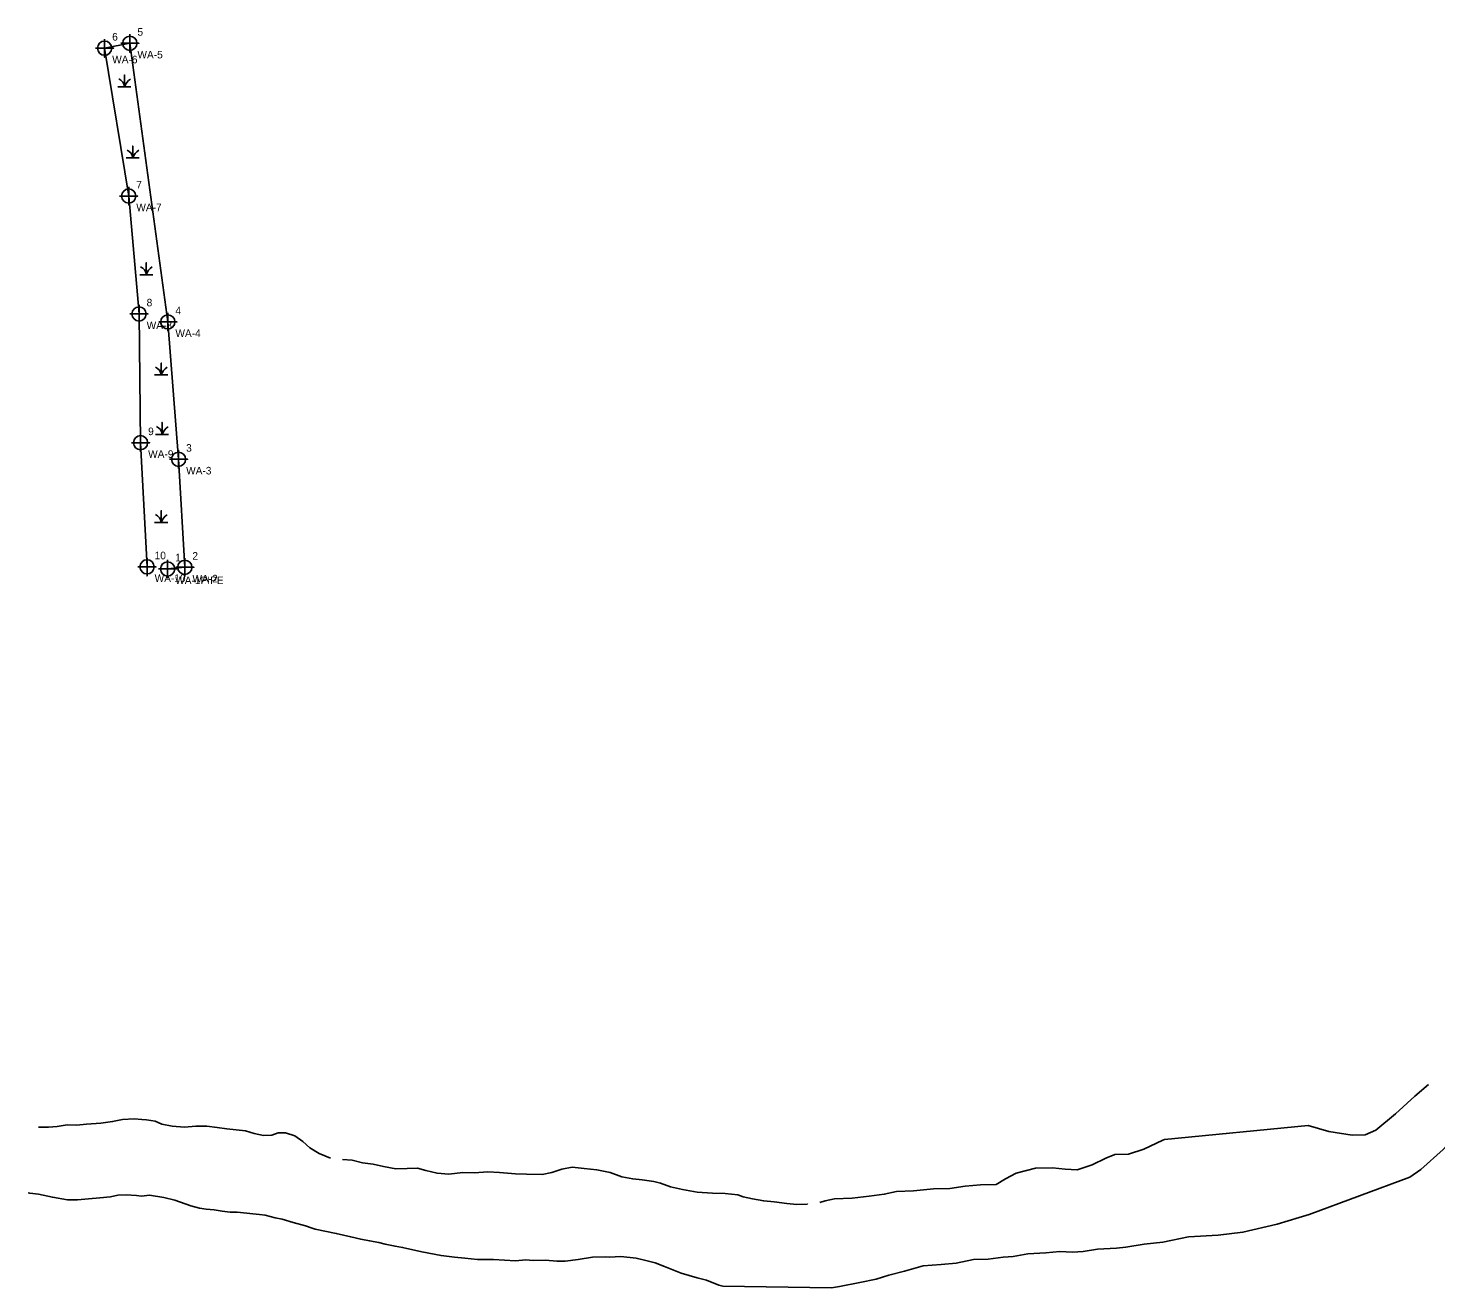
# Model space of a CAD drawing. Extents: x 1175766 to 1177869, y 922754 to 923618.
# Drawn here: x 1176876.9 to 1177341.6, y 922799.6 to 923215.6 of the extents above; entities that cross this region are included whole.
import ezdxf

# ---------------------------------------------------------------- set-up
doc = ezdxf.new("R2010")
doc.units = 0
for name, color, linetype in [('Default', 7, 'Continuous'), ('Prop North Arrow NAD83 for Plan Sheets CELL', 7, 'Continuous'), ('Sheet Data Field CELL', 7, 'Continuous'), ('Sheet Plot Border Inside CELL', 7, 'Continuous'), ('Sheet Plot Border Outside CELL', 7, 'Continuous')]:
    doc.layers.add(name, color=color, linetype=linetype)

msp = doc.modelspace()

# ---------------------------------------------------------------- linework, layer by layer
at = {"layer": 'Default'}
for points in [[(1176902.17, 923211.97), (1176902.17, 923205.97), (1176902.17, 923208.97), (1176905.17, 923208.97), (1176899.17, 923208.97)], [(1176910.5, 923213.58), (1176910.5, 923207.58), (1176910.5, 923210.58), (1176913.5, 923210.58), (1176907.5, 923210.58)], [(1176910.13, 923163.13), (1176910.13, 923157.13), (1176910.13, 923160.13), (1176913.13, 923160.13), (1176907.13, 923160.13)], [(1176913.54, 923124.19), (1176913.54, 923118.19), (1176913.54, 923121.19), (1176916.54, 923121.19), (1176910.54, 923121.19)], [(1176923.04, 923121.57), (1176923.04, 923115.57), (1176923.04, 923118.57), (1176926.04, 923118.57), (1176920.04, 923118.57)], [(1176914.03, 923081.67), (1176914.03, 923075.67), (1176914.03, 923078.67), (1176917.03, 923078.67), (1176911.03, 923078.67)], [(1176926.58, 923076.19), (1176926.58, 923070.19), (1176926.58, 923073.19), (1176929.58, 923073.19), (1176923.58, 923073.19)], [(1176916.18, 923040.67), (1176916.18, 923034.67), (1176916.18, 923037.67), (1176919.18, 923037.67), (1176913.18, 923037.67)], [(1176922.97, 923039.98), (1176922.97, 923033.98), (1176922.97, 923036.98), (1176925.97, 923036.98), (1176919.97, 923036.98)], [(1176928.65, 923040.53), (1176928.65, 923034.53), (1176928.65, 923037.53), (1176931.65, 923037.53), (1176925.65, 923037.53)]]:
    msp.add_lwpolyline(points, dxfattribs=at)
for centre in [(1176902.17, 923208.97), (1176910.5, 923210.58), (1176910.13, 923160.13), (1176913.54, 923121.19), (1176923.04, 923118.57), (1176914.03, 923078.67), (1176926.58, 923073.19), (1176916.18, 923037.67), (1176922.97, 923036.98), (1176928.65, 923037.53)]:
    msp.add_circle(centre, 2.34, dxfattribs=at)
at = {"layer": 'Prop North Arrow NAD83 for Plan Sheets CELL'}
for points in [[(1177339.21, 922866.73), (1177334.72, 922862.9), (1177328.29, 922857.07), (1177321.83, 922851.58), (1177318.27, 922850.07), (1177314.02, 922850), (1177306.26, 922851.18), (1177299.46, 922853.15)], [(1177352.29, 922852.66), (1177350.81, 922851.68), (1177347.22, 922848.81), (1177344.06, 922845.22), (1177336.7, 922838.67), (1177333.09, 922836.07)]]:
    msp.add_lwpolyline(points, dxfattribs=at)
at = {"layer": 'Sheet Data Field CELL'}
for p, q in [((1177252.08, 922848.53), (1177299.46, 922853.15)), ((1177299.79, 922823.82), (1177333.09, 922836.07)), ((1177106.25, 922800.15), (1177142.15, 922799.56))]:
    msp.add_line(p, q, dxfattribs=at)
for points in [[(1176914.44, 922855.16), (1176911.91, 922855.42), (1176908.11, 922855.16), (1176904.81, 922854.47), (1176900.96, 922853.93), (1176896.2, 922853.58), (1176892.88, 922853.27), (1176889.85, 922853.35), (1176886.49, 922852.81), (1176883.61, 922852.59), (1176880.83, 922852.59), (1176880.35, 922852.59)], [(1176976.7, 922842.38), (1176973.02, 922843.98), (1176969.91, 922845.78), (1176967.64, 922847.92), (1176965, 922849.73), (1176961.85, 922850.79), (1176959.5, 922850.78), (1176957.39, 922850), (1176954.58, 922849.9), (1176951.51, 922850.56), (1176948.71, 922851.4), (1176945.59, 922851.74), (1176942.49, 922852.07), (1176939.33, 922852.57), (1176935.9, 922852.94), (1176932.24, 922852.98), (1176928.56, 922852.6), (1176924.48, 922852.93), (1176921.1, 922853.63), (1176918.82, 922854.66), (1176915.95, 922855), (1176914.44, 922855.16)], [(1177252.08, 922848.53), (1177251.46, 922848.33), (1177245.26, 922845.31), (1177240.14, 922843.76), (1177235.67, 922843.57), (1177232.75, 922842.34), (1177228.24, 922840.19), (1177223.25, 922838.55), (1177219.27, 922838.75), (1177215.12, 922839.17), (1177209.43, 922839.12), (1177203.06, 922837.42), (1177199.61, 922835.6), (1177196.47, 922833.65), (1177191.3, 922833.58), (1177186.24, 922833.11), (1177181.24, 922832.39), (1177175.83, 922832.22), (1177169.22, 922831.56), (1177163.62, 922831.35), (1177159.53, 922830.47), (1177154.54, 922829.8), (1177148.97, 922829.15), (1177143.17, 922828.94), (1177140.04, 922828.31), (1177138.27, 922827.7)], [(1177134.25, 922827.2), (1177134.25, 922827.2), (1177130.66, 922827.13), (1177127.35, 922827.47), (1177123.16, 922827.94), (1177119.78, 922828.29), (1177116, 922828.97), (1177112.93, 922829.64), (1177111.23, 922830.31), (1177107.04, 922830.75), (1177102.8, 922830.84), (1177097.83, 922831.18), (1177092.96, 922832.04), (1177088.93, 922832.9), (1177085.73, 922834.11), (1177083.47, 922834.7), (1177079.68, 922835.18), (1177076.53, 922835.51), (1177072.96, 922836.2), (1177069.09, 922837.61), (1177064.65, 922838.55), (1177060.44, 922838.99), (1177056.56, 922839.39), (1177053.09, 922838.78), (1177049.84, 922837.64), (1177046.59, 922836.95), (1177041.47, 922837.05), (1177037.77, 922837.18), (1177032.56, 922837.7), (1177028.69, 922837.83), (1177024.25, 922837.59), (1177020.44, 922837.62), (1177015.81, 922837.11), (1177011.93, 922837.42), (1177008.26, 922838.31), (1177005.44, 922839.14), (1177002.03, 922839.02), (1176998.34, 922838.86), (1176994.27, 922839.63), (1176990.81, 922840.45), (1176987.26, 922840.9), (1176983.86, 922841.69), (1176980.7, 922841.96)], [(1176971.71, 922818.99), (1176970.64, 922819.32), (1176968.5, 922820.02), (1176964.4, 922821.11), (1176960.8, 922822.29), (1176958.49, 922822.69), (1176955.22, 922823.56), (1176953.27, 922823.76), (1176951.1, 922823.99), (1176949.15, 922824.19), (1176945.96, 922824.53), (1176943.67, 922824.6), (1176940.99, 922824.88), (1176938.31, 922825.28), (1176935.74, 922825.57), (1176933.49, 922825.82), (1176930.66, 922826.7), (1176925.39, 922828.49), (1176921.7, 922829.36), (1176916.94, 922830.13), (1176914.38, 922829.87), (1176912.66, 922830.06), (1176909.33, 922830.27), (1176906.56, 922830.2), (1176904.12, 922829.64), (1176900.58, 922829.31), (1176896.8, 922828.93), (1176893.27, 922828.68), (1176889.93, 922828.65), (1176884.95, 922829.48), (1176880.34, 922830.49), (1176877.44, 922830.8), (1176876.93, 922830.93)], [(1177299.79, 922823.82), (1177296.54, 922822.74), (1177289.24, 922820.61), (1177277.94, 922817.94), (1177269.74, 922817.01), (1177259.97, 922816.36), (1177251.51, 922814.67), (1177245.33, 922814.03), (1177239.27, 922813.02), (1177236.22, 922812.68), (1177230, 922812.29), (1177225.18, 922811.53), (1177221.64, 922811.38), (1177217.54, 922811.55), (1177212.84, 922811.07), (1177206.98, 922810.75), (1177202.1, 922809.92), (1177198.79, 922809.7), (1177193.85, 922809.08), (1177189, 922808.89), (1177183.26, 922807.72), (1177178.35, 922807.24), (1177172.4, 922806.78), (1177166.21, 922805.06), (1177161.07, 922803.7), (1177156.83, 922802.39), (1177151.53, 922801.36), (1177144.82, 922800.06), (1177142.15, 922799.56)], [(1177106.25, 922800.15), (1177104.89, 922800.47), (1177100.9, 922802.08), (1177097.74, 922802.87), (1177092.54, 922804.4), (1177087.01, 922806.65), (1177083.87, 922807.8), (1177080.83, 922808.61), (1177077.69, 922809.32), (1177075.69, 922809.53), (1177072.5, 922809.86), (1177068.97, 922809.66), (1177067.46, 922809.82), (1177063.25, 922809.73), (1177058.48, 922808.93), (1177054.19, 922808.4), (1177051.43, 922808.41), (1177047.77, 922808.69), (1177043.67, 922808.58), (1177041.18, 922808.84), (1177037.76, 922808.47), (1177030.56, 922808.91), (1177025.26, 922808.92), (1177021.06, 922809.38), (1177017.71, 922809.74), (1177013.22, 922810.21), (1177006.91, 922811.5), (1177000.51, 922812.92), (1176998.04, 922813.31), (1176994.82, 922814.01), (1176992.66, 922814.54), (1176989.67, 922815.13), (1176986.75, 922815.61), (1176983.43, 922816.36), (1176978.62, 922817.53), (1176971.71, 922818.99)]]:
    msp.add_lwpolyline(points, dxfattribs=at)
at = {"layer": 'Sheet Plot Border Inside CELL'}
msp.add_lwpolyline([(1176922.97, 923036.98), (1176928.65, 923037.53), (1176926.58, 923073.19), (1176923.04, 923118.57), (1176910.5, 923210.58), (1176902.17, 923208.97), (1176910.13, 923160.13), (1176913.54, 923121.19), (1176914.03, 923078.67), (1176916.18, 923037.67)], dxfattribs=at)
at = {"layer": 'Sheet Plot Border Outside CELL'}
for p, q in [((1176908.72, 923197.99), (1176908.72, 923197.99)), ((1176911.47, 923174.49), (1176911.47, 923174.49)), ((1176915.92, 923135.94), (1176915.92, 923135.94)), ((1176920.84, 923102.81), (1176920.84, 923102.81)), ((1176921.15, 923083.19), (1176921.15, 923083.19)), ((1176920.84, 923054.11), (1176920.84, 923054.11))]:
    msp.add_line(p, q, dxfattribs=at)
for points in [[(1176906.57, 923196.21), (1176908.72, 923196.21), (1176908.72, 923200.15), (1176908.72, 923196.21), (1176910.87, 923196.21)], [(1176909.32, 923172.7), (1176911.47, 923172.7), (1176911.47, 923176.65), (1176911.47, 923172.7), (1176913.62, 923172.7)], [(1176913.77, 923134.16), (1176915.92, 923134.16), (1176915.92, 923138.1), (1176915.92, 923134.16), (1176918.07, 923134.16)], [(1176918.69, 923101.03), (1176920.84, 923101.03), (1176920.84, 923104.98), (1176920.84, 923101.03), (1176922.99, 923101.03)], [(1176919, 923081.41), (1176921.15, 923081.41), (1176921.15, 923085.35), (1176921.15, 923081.41), (1176923.3, 923081.41)], [(1176918.69, 923052.33), (1176920.84, 923052.33), (1176920.84, 923056.27), (1176920.84, 923052.33), (1176922.99, 923052.33)]]:
    msp.add_lwpolyline(points, dxfattribs=at)
for centre, radius, start, end in [((1176905.65, 923195.99), 3.07, 4.1403, 67.535), ((1176913.28, 923194.69), 4.81, 122.1274, 161.6222), ((1176908.4, 923172.48), 3.07, 4.1403, 67.535), ((1176916.03, 923171.19), 4.81, 122.1274, 161.6222), ((1176912.85, 923133.94), 3.07, 4.1403, 67.535), ((1176920.48, 923132.64), 4.81, 122.1274, 161.6222), ((1176917.77, 923100.81), 3.07, 4.1403, 67.535), ((1176925.4, 923099.52), 4.81, 122.1274, 161.6222), ((1176918.09, 923081.18), 3.07, 4.1403, 67.535), ((1176925.71, 923079.89), 4.81, 122.1274, 161.6222), ((1176917.77, 923052.11), 3.07, 4.1403, 67.535), ((1176925.4, 923050.81), 4.81, 122.1274, 161.6222)]:
    msp.add_arc(centre, radius, start, end, dxfattribs=at)

# ---------------------------------------------------------------- texts
at = {"layer": 'Default'}
for s, p in [('5', (1176913, 923213.08)), ('6', (1176904.67, 923211.47)), ('WA-6', (1176904.67, 923203.97)), ('WA-5', (1176913, 923205.58)), ('7', (1176912.63, 923162.63)), ('WA-7', (1176912.63, 923155.13)), ('8', (1176916.04, 923123.69)), ('4', (1176925.54, 923121.07)), ('WA-8', (1176916.04, 923116.19)), ('WA-4', (1176925.54, 923113.57)), ('9', (1176916.53, 923081.17)), ('WA-9', (1176916.53, 923073.67)), ('3', (1176929.08, 923075.69)), ('WA-3', (1176929.08, 923068.19)), ('10', (1176918.68, 923040.17)), ('1', (1176925.47, 923039.48)), ('2', (1176931.15, 923040.03)), ('WA-10', (1176918.68, 923032.67)), ('WA-1PIPE', (1176925.47, 923031.98)), ('WA-2', (1176931.15, 923032.53))]:
    msp.add_text(s, height=2.5, dxfattribs=at).set_placement(p)

doc.saveas('drawing.dxf')
